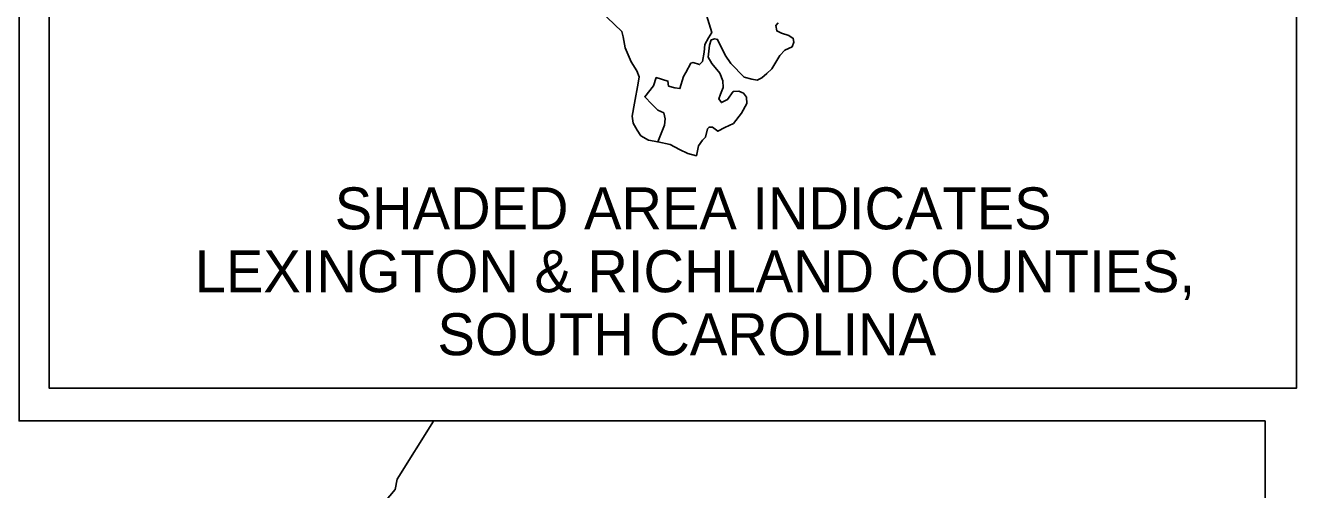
# Model space of a CAD drawing. Extents: x 1936118 to 1997618, y 780614 to 828614.
# Drawn here: x 1979434 to 1997618, y 810402 to 817040 of the extents above; entities that cross this region are included whole.
import ezdxf

# ---------------------------------------------------------------- set-up
doc = ezdxf.new("R2010")
doc.units = 0
for name, color, linetype in [('RD_EX_H2O_BlueLn', 7, 'Continuous'), ('RD_SHT_Bndy', 7, 'Continuous'), ('RD_SHT_Misc1', 7, 'Continuous'), ('RD_SHT_ShtClip', 7, 'Continuous'), ('RD_SHT_TX', 7, 'Continuous')]:
    doc.layers.add(name, color=color, linetype=linetype)

msp = doc.modelspace()

# ---------------------------------------------------------------- linework, layer by layer
at = {"layer": 'RD_EX_H2O_BlueLn'}
msp.add_lwpolyline([(1985270, 811384), (1985270, 811381), (1984750, 810550), (1984723, 810402), (1984570, 810222), (1984448, 810146), (1984298, 810008), (1984296, 809787), (1984022, 809563), (1983872, 809563), (1983634, 809275), (1983391, 809092), (1983086, 808985), (1982910, 808808), (1982783, 808808), (1982571, 808907), (1982481, 808908), (1982361, 808623), (1982210, 808328), (1981841, 807931), (1981841, 807833)], dxfattribs=at)
at = {"layer": 'RD_SHT_Bndy'}
msp.add_lwpolyline([(1979773, 828614), (1997618, 828614), (1997618, 811853), (1979773, 811853)], close=True, dxfattribs=at)
at = {"layer": 'RD_SHT_Misc1'}
for p, q in [((1987650, 817252), (1987965, 816953)), ((1990170, 817038), (1990204, 817079)), ((1990183, 816962), (1990170, 817038)), ((1987965, 816953), (1987986, 816876)), ((1987986, 816876), (1988015, 816718)), ((1990248, 816929), (1990183, 816962)), ((1990354, 816896), (1990248, 816929)), ((1990418, 816854), (1990354, 816896)), ((1990425, 816802), (1990418, 816854)), ((1988015, 816718), (1988099, 816521)), ((1989202, 816584), (1989222, 816758)), ((1989222, 816758), (1989246, 816833)), ((1989246, 816833), (1989295, 816850)), ((1989295, 816850), (1989335, 816839)), ((1989335, 816839), (1989443, 816616)), ((1990226, 816608), (1990297, 816686)), ((1990297, 816686), (1990402, 816736)), ((1990402, 816736), (1990425, 816802)), ((1988099, 816521), (1988182, 816389)), ((1989254, 816494), (1989202, 816584)), ((1989370, 816357), (1989254, 816494)), ((1989443, 816616), (1989524, 816497)), ((1989524, 816497), (1989714, 816299)), ((1990111, 816420), (1990226, 816608)), ((1988182, 816389), (1988212, 816306)), ((1989410, 816249), (1989370, 816357)), ((1989968, 816291), (1990041, 816351)), ((1990041, 816351), (1990111, 816420)), ((1988200, 816215), (1988146, 815930)), ((1988212, 816306), (1988200, 816215)), ((1989379, 816059), (1989415, 816151)), ((1989415, 816151), (1989410, 816249)), ((1989714, 816299), (1989826, 816270)), ((1989826, 816270), (1989903, 816259)), ((1989903, 816259), (1989968, 816291)), ((1989355, 815988), (1989379, 816059)), ((1989390, 815937), (1989355, 815988)), ((1989479, 815980), (1989390, 815937)), ((1989560, 816094), (1989479, 815980)), ((1989640, 816101), (1989560, 816094)), ((1989705, 816069), (1989640, 816101)), ((1989748, 816012), (1989705, 816069)), ((1989754, 815923), (1989748, 816012)), ((1988146, 815930), (1988114, 815740)), ((1989561, 815639), (1989679, 815785)), ((1989679, 815785), (1989754, 815923)), ((1988114, 815740), (1988128, 815641)), ((1988128, 815641), (1988184, 815540)), ((1989193, 815561), (1989215, 815585)), ((1989215, 815585), (1989261, 815584)), ((1989261, 815584), (1989341, 815526)), ((1989437, 815578), (1989561, 815639)), ((1988184, 815540), (1988238, 815463)), ((1988238, 815463), (1988345, 815397)), ((1989062, 815319), (1989119, 815399)), ((1989119, 815399), (1989162, 815440)), ((1989162, 815440), (1989193, 815561)), ((1989341, 815526), (1989437, 815578)), ((1988345, 815397), (1988480, 815373)), ((1988480, 815373), (1988657, 815339)), ((1988657, 815339), (1988790, 815265)), ((1988790, 815265), (1988911, 815206)), ((1989032, 815175), (1989062, 815319)), ((1988911, 815206), (1989032, 815175))]:
    msp.add_line(p, q, dxfattribs=at)
for points in [[(1989175, 817186), (1989252, 816939), (1989204, 816862), (1989154, 816767), (1989143, 816658), (1989119, 816522), (1989077, 816481), (1988987, 816508), (1988954, 816499), (1988879, 816365), (1988848, 816309), (1988796, 816136), (1988723, 816146), (1988634, 816172), (1988626, 816243), (1988457, 816295), (1988417, 816175), (1988293, 816021), (1988394, 815914), (1988479, 815828), (1988566, 815788), (1988587, 815706), (1988575, 815615), (1988480, 815373), (1988345, 815397), (1988238, 815463), (1988184, 815540), (1988128, 815641), (1988114, 815740), (1988146, 815930), (1988200, 816215), (1988212, 816306), (1988182, 816389), (1988099, 816521), (1988015, 816718), (1987986, 816876), (1987965, 816953), (1987650, 817252)], [(1987650, 817252), (1987965, 816953), (1987986, 816876), (1988015, 816718), (1988099, 816521), (1988182, 816389)], [(1988182, 816389), (1988212, 816306), (1988200, 816215), (1988146, 815930), (1988114, 815740), (1988128, 815641), (1988184, 815540), (1988238, 815463), (1988345, 815397), (1988480, 815373), (1988657, 815339), (1988790, 815265), (1988911, 815206), (1989032, 815175), (1989062, 815319), (1989119, 815399), (1989162, 815440), (1989193, 815561), (1989215, 815585), (1989261, 815584), (1989341, 815526), (1989437, 815578), (1989561, 815639), (1989679, 815785), (1989754, 815923), (1989748, 816012), (1989705, 816069), (1989640, 816101), (1989560, 816094), (1989479, 815980), (1989390, 815937), (1989355, 815988), (1989379, 816059), (1989415, 816151), (1989410, 816249), (1989370, 816357), (1989254, 816494), (1989202, 816584), (1989222, 816758), (1989246, 816833), (1989295, 816850), (1989335, 816839), (1989443, 816616), (1989524, 816497), (1989714, 816299), (1989826, 816270), (1989903, 816259), (1989968, 816291), (1990041, 816351), (1990111, 816420), (1990226, 816608), (1990297, 816686), (1990402, 816736), (1990425, 816802), (1990418, 816854), (1990354, 816896), (1990248, 816929), (1990183, 816962), (1990170, 817038), (1990204, 817079)], [(1990204, 817079), (1990170, 817038), (1990183, 816962), (1990248, 816929), (1990354, 816896), (1990418, 816854), (1990425, 816802), (1990402, 816736), (1990297, 816686), (1990226, 816608), (1990111, 816420), (1990041, 816351), (1989968, 816291), (1989903, 816259), (1989826, 816270), (1989714, 816299), (1989524, 816497), (1989443, 816616), (1989335, 816839), (1989295, 816850), (1989246, 816833), (1989222, 816758), (1989202, 816584), (1989254, 816494), (1989370, 816357), (1989410, 816249), (1989415, 816151), (1989379, 816059), (1989355, 815988), (1989390, 815937), (1989479, 815980), (1989560, 816094), (1989640, 816101), (1989705, 816069), (1989748, 816012), (1989754, 815923), (1989679, 815785), (1989561, 815639), (1989437, 815578), (1989341, 815526), (1989261, 815584), (1989215, 815585), (1989193, 815561), (1989162, 815440), (1989119, 815399), (1989062, 815319), (1989032, 815175), (1988911, 815206), (1988790, 815265), (1988657, 815339), (1988480, 815373), (1988575, 815615), (1988587, 815706), (1988566, 815788), (1988479, 815828), (1988394, 815914), (1988293, 816021), (1988417, 816175), (1988457, 816295), (1988626, 816243), (1988634, 816172), (1988723, 816146), (1988796, 816136), (1988848, 816309), (1988879, 816365), (1988954, 816499), (1988987, 816508), (1989077, 816481), (1989119, 816522), (1989143, 816658), (1989154, 816767), (1989204, 816862), (1989252, 816939), (1989175, 817186)]]:
    msp.add_lwpolyline(points, dxfattribs=at)
at = {"layer": 'RD_SHT_ShtClip'}
msp.add_lwpolyline([(1936683, 827674), (1979343, 827674), (1979343, 811384), (1997169, 811384), (1997169, 788874), (1947786, 788874), (1945387, 788861), (1936683, 788861)], close=True, dxfattribs=at)

# ---------------------------------------------------------------- texts
at = {"layer": 'RD_SHT_TX'}
for s, p in [('SHADED AREA INDICATES', (1983859, 814124)), ('LEXINGTON & RICHLAND COUNTIES,', (1981856, 813224)), ('SOUTH CAROLINA', (1985328, 812324))]:
    msp.add_text(s, height=600, rotation=360, dxfattribs=at).set_placement(p)

doc.saveas('drawing.dxf')
